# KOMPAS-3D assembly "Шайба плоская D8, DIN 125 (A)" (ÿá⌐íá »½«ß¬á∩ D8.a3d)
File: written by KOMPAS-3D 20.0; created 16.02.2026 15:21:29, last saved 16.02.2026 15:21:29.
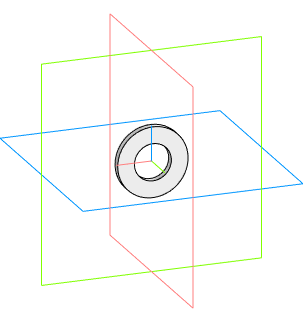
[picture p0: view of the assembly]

Document properties: Автор: admin; Полное имя файла: P:\INSTART\Технический отдел\ОР\Прочие задачи\КД на номенклатурный ряд\КД на типоразмеры дросселей\Сетевые дроссели ISF\ISF-4\Тип 1\ISF-132_256-4\0723\Новая папка\Шайба плоская D8.a3d

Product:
- Part/product: Шайба плоская D8  | designation DIN 125 (A)
  - Component [detail]: Шайба A.8.37 ГОСТ 11371-78  | source file: Шайба A.8.37 ГОСТ 11371-78.m3d

Referenced files in P:\INSTART\Технический отдел\ОР\Прочие задачи\КД на номенклатурный ряд\КД на типоразмеры дросселей\Сетевые дроссели ISF\ISF-4\Тип 1\ISF-132_256-4\0723\Новая папка\: Шайба A.8.37 ГОСТ 11371-78.m3d
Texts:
  DIN 125 (A)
